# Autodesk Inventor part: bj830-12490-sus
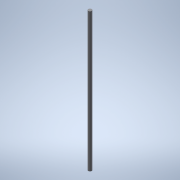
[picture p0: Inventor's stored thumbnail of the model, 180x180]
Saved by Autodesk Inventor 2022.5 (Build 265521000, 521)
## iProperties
Created: 2016-12
Part Number: bj830-12490-sus
Material: 一般
Document SubType Name: Modeling
Designer: imaocorp
Density: 1 g/cm^3
Appearance: 既定
Author: imaocorp
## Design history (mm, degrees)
node "bj830-12490-sus.x_t1"
node "bj830-12490-sus"
node "Base1"
